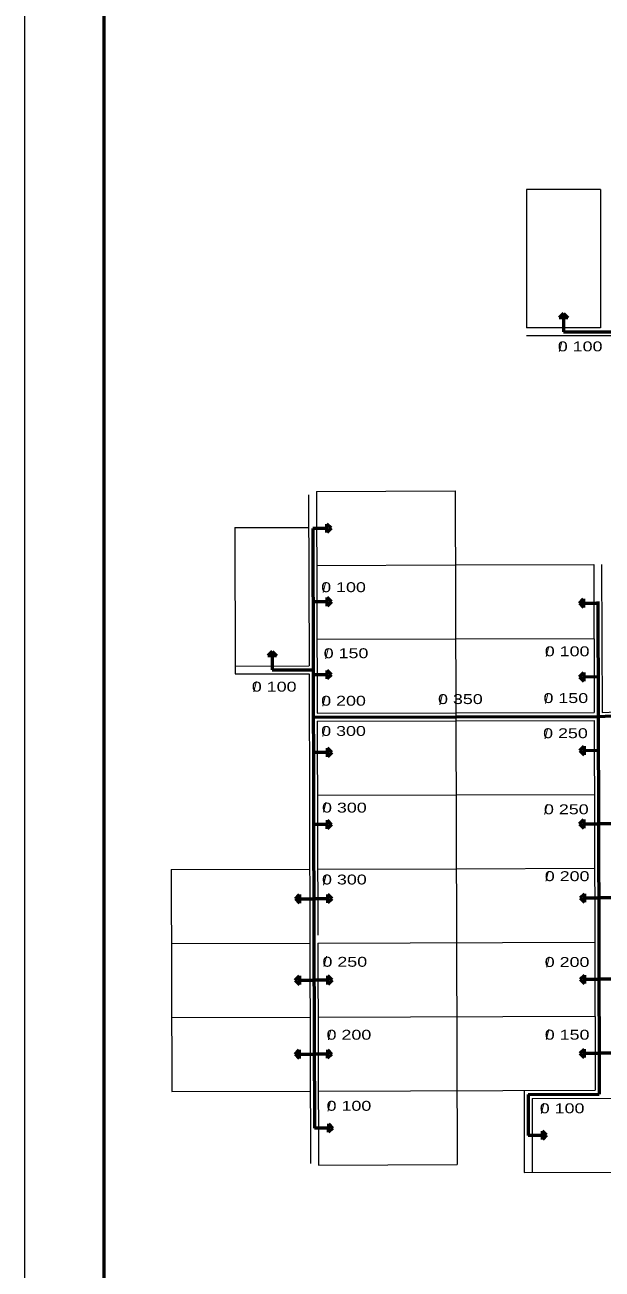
# Model space of a CAD drawing. Extents: x 312964 to 351929, y 9004151 to 9034973.
# Drawn here: x 342096 to 343555, y 9028567 to 9031712 of the extents above; entities that cross this region are included whole.
import ezdxf
from ezdxf.enums import TextEntityAlignment as Align

# ---------------------------------------------------------------- set-up
doc = ezdxf.new("R2010")
doc.units = 0
doc.header["$LTSCALE"] = 10
doc.layers.add('1', color=7, linetype='Continuous', lineweight=13)
doc.layers.add('2', color=7, linetype='Continuous', lineweight=53)

msp = doc.modelspace()

# ---------------------------------------------------------------- linework, layer by layer
at = {"layer": '1'}
for p, q in [((342096.46, 9030772.79), (342096.46, 9034972.79)), ((343364.24, 9031296.36), (343364.24, 9030946.36)), ((343551.24, 9031296.36), (343364.24, 9031296.36)), ((343551.24, 9031296.36), (343551.24, 9030946.36)), ((343551.24, 9030946.36), (343364.24, 9030946.36)), ((343517.51, 9030946.36), (343364.24, 9030946.36)), ((342833.51, 9030533.31), (343183.51, 9030534.35)), ((342833.51, 9030533.31), (342835.17, 9029972.32)), ((343183.51, 9030534.35), (343188.55, 9028831.36)), ((342813.54, 9030524.2), (342814.82, 9030092.26)), ((342626.78, 9030441.7), (342813.78, 9030442.26)), ((342626.78, 9030441.7), (342627.88, 9030071.7)), ((342834.07, 9030346.31), (343184.07, 9030347.35)), ((343184.07, 9030347.35), (343534.07, 9030348.39)), ((343534.07, 9030348.39), (343535.17, 9029974.39)), ((343554.07, 9030348.45), (343555.17, 9029974.45)), ((342834.62, 9030159.32), (343184.62, 9030160.35)), ((343184.62, 9030160.35), (343534.62, 9030161.39)), ((342627.82, 9030091.7), (342814.82, 9030092.26)), ((342627.88, 9030071.7), (342814.88, 9030072.26)), ((343555.17, 9029974.45), (343957.65, 9029995.46)), ((342835.17, 9029972.32), (343185.17, 9029973.35)), ((343185.17, 9029973.35), (343535.17, 9029974.39)), ((342835.23, 9029952.32), (342836.83, 9029411.32)), ((343535.23, 9029954.39), (343536.89, 9029393.39)), ((342835.79, 9029765.32), (343185.79, 9029766.35)), ((343185.79, 9029766.35), (343535.78, 9029767.39)), ((342466.34, 9029577.22), (342816.34, 9029578.26)), ((342466.34, 9029577.22), (342468, 9029016.23)), ((342836.89, 9029391.32), (343536.89, 9029393.39)), ((342836.89, 9029391.32), (343536.89, 9029393.39)), ((343536.89, 9029393.39), (343538, 9029019.39)), ((342466.89, 9029390.22), (342816.89, 9029391.26)), ((342466.9, 9029390.22), (342816.89, 9029391.26)), ((342836.89, 9029391.32), (342838.55, 9028830.32)), ((342467.45, 9029203.23), (342817.45, 9029204.26)), ((342837.45, 9029204.32), (343537.44, 9029206.39)), ((342468, 9029016.23), (342818, 9029017.26)), ((342838, 9029017.32), (343538, 9029019.39)), ((343358, 9029018.86), (343358.61, 9028811.86)), ((343378.06, 9028998.92), (343728.06, 9028999.95)), ((343378.06, 9028998.92), (343378.61, 9028811.92)), ((342838.55, 9028830.32), (343188.55, 9028831.36)), ((343358.61, 9028811.86), (343728.61, 9028812.95))]:
    msp.add_line(p, q, dxfattribs=at)
at = {"layer": '1', "lineweight": 53}
msp.add_line((342296.46, 9026772.79), (342296.46, 9034472.79), dxfattribs=at)
at = {"layer": '1'}
for points in [[(343995.24, 9030926.36), (343571.24, 9030926.36), (343364.24, 9030926.36)], [(348036.46, 9030772.79), (348036.46, 9026572.79), (342096.46, 9026572.79), (342096.46, 9030772.79)], [(342814.88, 9030072.26), (342816.89, 9029391.26), (342818.54, 9028834.2)], [(342835.23, 9029952.32), (343185.23, 9029953.35), (343535.23, 9029954.39)], [(342836.34, 9029578.32), (343186.34, 9029579.35), (343536.34, 9029580.39)]]:
    msp.add_lwpolyline(points, dxfattribs=at)
at = {"layer": '2'}
for p, q in [((343457.64, 9030982.99), (343446.82, 9030972.25)), ((343468.38, 9030972.17), (343446.82, 9030972.25)), ((343457.64, 9030982.99), (343468.38, 9030972.17)), ((343457.86, 9030972.21), (343457.74, 9030936.36)), ((343457.74, 9030936.36), (344355.24, 9030936.36)), ((342823.79, 9030439.79), (342826.86, 9029401.29)), ((342859.64, 9030439.66), (342823.79, 9030439.79)), ((342859.6, 9030429.14), (342859.68, 9030450.7)), ((342870.42, 9030439.89), (342859.6, 9030429.14)), ((342870.42, 9030439.89), (342859.68, 9030450.7)), ((342860.19, 9030253.73), (342824.34, 9030253.85)), ((342860.15, 9030243.21), (342860.23, 9030264.77)), ((342870.97, 9030253.95), (342860.15, 9030243.21)), ((342870.97, 9030253.95), (342860.23, 9030264.77)), ((343497.73, 9030250.58), (343508.54, 9030261.33)), ((343497.73, 9030250.58), (343508.47, 9030239.77)), ((343508.54, 9030261.33), (343508.47, 9030239.77)), ((343508.51, 9030250.81), (343544.35, 9030250.69)), ((342721.25, 9030128.61), (342710.43, 9030117.87)), ((342731.99, 9030117.79), (342710.43, 9030117.87)), ((342721.25, 9030128.61), (342731.99, 9030117.79)), ((342721.47, 9030117.83), (342721.35, 9030081.98)), ((342721.35, 9030081.98), (342824.85, 9030082.29)), ((342860.73, 9030069.7), (342824.89, 9030069.82)), ((342860.7, 9030059.18), (342860.77, 9030080.73)), ((342871.51, 9030069.92), (342860.7, 9030059.18)), ((342871.51, 9030069.92), (342860.77, 9030080.73)), ((343498.28, 9030064.74), (343509.09, 9030075.48)), ((343498.28, 9030064.74), (343509.02, 9030053.92)), ((343509.09, 9030075.48), (343509.02, 9030053.92)), ((343509.06, 9030064.96), (343544.9, 9030064.84)), ((342825.2, 9029962.29), (343185.2, 9029963.35)), ((343185.2, 9029963.35), (343545.2, 9029964.42)), ((343545.2, 9029963.91), (343958.17, 9029985.48)), ((342861.32, 9029872.9), (342825.47, 9029873.02)), ((342861.28, 9029862.38), (342861.35, 9029883.94)), ((342872.1, 9029873.12), (342861.28, 9029862.38)), ((342872.1, 9029873.12), (342861.35, 9029883.94)), ((343498.83, 9029878.45), (343509.64, 9029889.2)), ((343498.83, 9029878.45), (343509.57, 9029867.64)), ((343509.64, 9029889.2), (343509.57, 9029867.64)), ((343509.61, 9029878.68), (343545.46, 9029878.56)), ((342860.75, 9029690.87), (342824.9, 9029690.99)), ((342860.71, 9029680.35), (342860.79, 9029701.91)), ((342871.53, 9029691.09), (342860.71, 9029680.35)), ((342871.53, 9029691.09), (342860.79, 9029701.91)), ((343498.27, 9029693.02), (343509.09, 9029703.76)), ((343498.27, 9029693.02), (343509.01, 9029682.2)), ((343509.09, 9029703.76), (343509.01, 9029682.2)), ((343509.05, 9029693.24), (343544.9, 9029693.12)), ((343580.75, 9029693), (343544.9, 9029693.12)), ((342779.93, 9029503.43), (342790.75, 9029514.17)), ((342779.93, 9029503.43), (342790.68, 9029492.61)), ((342790.75, 9029514.17), (342790.68, 9029492.61)), ((342790.71, 9029503.65), (342826.56, 9029503.53)), ((342862.41, 9029503.41), (342826.56, 9029503.53)), ((342862.37, 9029492.89), (342862.45, 9029514.45)), ((342873.19, 9029503.63), (342862.37, 9029492.89)), ((342873.19, 9029503.63), (342862.45, 9029514.45)), ((343499.93, 9029505.56), (343510.75, 9029516.3)), ((343499.93, 9029505.56), (343510.67, 9029494.74)), ((343510.75, 9029516.3), (343510.67, 9029494.74)), ((343510.71, 9029505.78), (343546.56, 9029505.66)), ((343582.41, 9029505.54), (343546.56, 9029505.66)), ((342826.86, 9029401.29), (342828.28, 9028923.79)), ((342779.84, 9029297.69), (342790.66, 9029308.43)), ((342779.84, 9029297.69), (342790.59, 9029286.87)), ((342790.66, 9029308.43), (342790.59, 9029286.87)), ((342790.62, 9029297.91), (342826.47, 9029297.79)), ((342862.32, 9029297.67), (342826.47, 9029297.79)), ((342862.28, 9029287.15), (342862.36, 9029308.71)), ((342873.1, 9029297.89), (342862.28, 9029287.15)), ((342873.1, 9029297.89), (342862.36, 9029308.71)), ((343499.84, 9029299.82), (343510.66, 9029310.56)), ((343499.84, 9029299.82), (343510.58, 9029289)), ((343510.66, 9029310.56), (343510.58, 9029289)), ((343510.62, 9029300.04), (343546.47, 9029299.92)), ((343582.32, 9029299.8), (343546.47, 9029299.92)), ((342779.13, 9029110.69), (342789.95, 9029121.43)), ((342779.13, 9029110.69), (342789.88, 9029099.87)), ((342789.95, 9029121.43), (342789.88, 9029099.87)), ((342789.92, 9029110.91), (342825.76, 9029110.79)), ((342861.61, 9029110.67), (342825.76, 9029110.79)), ((342861.58, 9029100.15), (342861.65, 9029121.71)), ((342872.39, 9029110.89), (342861.58, 9029100.15)), ((342872.39, 9029110.89), (342861.65, 9029121.71)), ((343499.13, 9029112.82), (343509.95, 9029123.56)), ((343499.13, 9029112.82), (343509.88, 9029102)), ((343509.95, 9029123.56), (343509.88, 9029102)), ((343509.91, 9029113.04), (343545.76, 9029112.92)), ((343581.61, 9029112.8), (343545.76, 9029112.92)), ((343368.03, 9029008.89), (343548.03, 9029009.42)), ((343368.03, 9029008.89), (343368.33, 9028905.39)), ((342864.12, 9028923.67), (342828.28, 9028923.79)), ((342864.09, 9028913.15), (342864.16, 9028934.71)), ((342874.91, 9028923.89), (342864.09, 9028913.15)), ((342874.91, 9028923.89), (342864.16, 9028934.71)), ((343404.18, 9028905.27), (343368.33, 9028905.39)), ((343404.15, 9028894.75), (343404.22, 9028916.31)), ((343414.96, 9028905.49), (343404.15, 9028894.75)), ((343414.96, 9028905.49), (343404.22, 9028916.31))]:
    msp.add_line(p, q, dxfattribs=at)
msp.add_lwpolyline([(343544.34, 9030254.92), (343546.86, 9029403.42), (343548.03, 9029009.42)], dxfattribs=at)

# ---------------------------------------------------------------- texts
at = {"layer": '2', "width": 1.35}
for s, p in [('0 100', (343499.69, 9030887.23)), ('0 100', (342901.74, 9030278.58)), ('0 150', (342908.08, 9030111.64)), ('0 100', (343466.84, 9030116.56)), ('0 100', (342726.48, 9030027.1)), ('0 350', (343197.04, 9029995.66)), ('0 150', (343463.53, 9029998.21)), ('0 200', (342901.74, 9029991.47)), ('0 300', (342901.74, 9029915.1)), ('0 250', (343462.62, 9029909.46)), ('0 300', (342903.84, 9029721.35)), ('0 250', (343464.73, 9029717.15)), ('0 300', (342903.84, 9029539.61)), ('0 200', (343466.84, 9029548.09)), ('0 250', (342904.96, 9029331.61)), ('0 200', (343466.71, 9029331.11)), ('0 200', (342915.4, 9029147.18)), ('0 150', (343466.81, 9029147.27)), ('0 100', (342915.4, 9028967.55)), ('0 100', (343454.14, 9028961.3))]:
    msp.add_text(s, height=25, dxfattribs=at).set_placement(p, align=Align.CENTER)
at = {"layer": '2'}
for p in [(343450.31, 9030886.58), (342853.43, 9030277.64), (342859.76, 9030110.22), (343417.22, 9030115.5), (342678.17, 9030026.74), (343415.22, 9029996.79), (342852.37, 9029990.05), (343148.28, 9029993.66), (342852.37, 9029913.68), (343414.05, 9029907.34), (342854.38, 9029721.97), (343413.21, 9029716.6), (342854.38, 9029538.11), (343416.38, 9029547.54), (342855.5, 9029332.23), (343418.36, 9029330.56), (342866.65, 9029146.64), (343417.49, 9029147.67), (342865.59, 9028966.16), (343404.83, 9028960.65)]:
    msp.add_text('/', height=25, dxfattribs=at).set_placement(p, align=Align.CENTER)

doc.saveas('drawing.dxf')
